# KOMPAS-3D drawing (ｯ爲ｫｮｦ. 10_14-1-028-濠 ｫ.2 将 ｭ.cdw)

Views: Вид 1
Referenced files in C:\Program Files\ASCON\KOMPAS-3D V10\Sys\: SPDS.lcs, Graphic.lcs
Referenced files: Планы вагончиков.cdw
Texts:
  Текст на чертеже
  Размерные надписи
  Шероховатость
  Линия-выноска #1
  Линия-выноска #2
  Линия-выноска #3
  Отклонения формы и база
  Заголовок таблицы
  Ячейка таблицы
  Стрелка вида
  Обозначение изменения
  Фигурная скобка
  Номер узла
  Марка координационной оси
  VRCB
  Выносная надпись
  Обозначение узла
  Марка/позиционное обозначение с линией-выноской
  Марка/позиционное обозначение на линии
  Марка/позиционное обозначение без линии-выноски
  Normal
  TXT
  Courier New Cyr
  txt
  Body Text
  heading 1
  Знак Знак Знак Знак Знак Знак
  Verdana
  Лит-Масса-Масштаб
  Материал-Предприятие
  MS Sans Serif
  Simplex
  Txt
  Title Specification
  Body Specification ( left align )
  Body Specificaton ( centered )
  Без имени
  Additional DXF text style 0
  Обычный
  Термин
  Список определений
  Адрес
  Цитаты
  Форматированный
  Courier New
  Z-конец формы
  Z-начало формы
  ТекстШаг1
  Денис
  heading 2
  AGOpus
  footer
  Title
  ООббыыччнныыйй
  Definition Term
  Definition List
  Address
  Blockquote
  Preformatted
  z-Bottom of Form
  z-Top of Form
  header
  heading 8
  heading 3
  heading 6
  heading 7
  russ
  ТТееррммиинн
  ССппииссоокк ооппррееддееллеенниийй
  ААддрреесс
  ЦЦииттааттыы
  ФФооррммааттиирроовваанннныыйй
  Z-ккооннеецц ффооррммыы
  Z-ннааччааллоо ффооррммыы
  Абзац Знак
  heading 4
  heading 5
  heading 9
  GOST 2.304 type A
  rustxt
  цепи
  ссылки
  Маркировка
  Подпись в квадратике
  табл
  ЗОНА_привяз
  маркировка
  ГОСТ_МНЕ
  ESK - Обозначение
  текст переноса
  Тексты. 3,2
  Body Text 3
  клеммы, контакты
  тексты табл
  ISOCP
  HeliosLight
  Pa3
  Pa1
  Шрифт 2.5
  Заголовки
  RUSTXT
  NormalParagraphStyle
  Три с половиной
  style2
  Table Contents
  Table Heading
  CNBNDG+TimesNewRoman
  Subtitle
  ISOCPEUR
  Текст 3,5
  Tahoma
  План ПС
  Существующее оборудование
  Дороги
  Оси, размеры
  Позиции,таблицы
  Топосъемка
  Демонтаж
  изм.1
  Вертикалка
  створ поз.2
  в.ЗРУ 108,86
  в.вх.105,84
  ЗРУ-110 кВ
  в.вх.105,54
  ЗРУ-35 кВ
  в.вх.105,48
  в.вх.103,67
  в.вх.105,89
  в.вх.103,72
  в.ЗРУ 108,68
  в.вх.105,56
  в.вх.105,47
  ЗРУ-6 кВ
  в.ош.103,82
  в.ош.103,84
  в.ош.103,80
  в.кр.п.111,27
  в.каб.112,57
  кр-100,99
  кр-100,45
  кр-100,41
  кр-101,03
  кр-101,02
  кр-100,56
  кр-100,70
  кр-100,94
  РП 1
  РП 2
  ТСН-2
  ТСН-1
  ПС 110 кВ Опорная
  Данная проектная документация разработана на основании технического задания на
  проектирование, межевого плана, кадастровой выписки о земельном участке №8900/212/12-15995
  от 14.09.2012г., материалов инженерно-топографических изысканий, выполненных ООО "Северный
  Стандарт" в 2012г.
  Технические решения,принятые в чертежах, соответствуют действующим нормам, правилам и
  стандартам.
  Номер
  на плане
  Экспликация зданий и сооружений
  Существующие здания и сооружения
  Проектируемые здания и сооружения
  Трансформатор силовой масляный трехфазный
  трехобмоточный ТДТН 40000/110 ХЛ1
  Реакторная 1Т
  Реакторная 2Т
  Маслосборник
  Очистная установка
  Резервуар
  Условные обозначения:
  - Аварийный маслоотвод
  - Напорный трубопровод подачи стоков
  - Трубопровод очищенного стока
  МП1
  МП2
  уг.2
  уг.1
  STROT_RGB_128_32_0_SC_1_THICK_0.18
  CONTI_RGB_0_0_0_THICK_0.18
  POLYLINE_STYLE_0.30_RGB_0_0_0
  POLYLINE_STYLE_0.18_RGB_0_0_0
  ACAD_ISO02W100_RGB_0_0_255_SC_1_THICK_0.3
  POLYLINE_STYLE_0.60_RGB_0_0_255
  ACAD_ISO02W100_RGB_0_0_0_SC_1_THICK_0.15
  POLYLINE_STYLE_0.18_RGB_255_0_0
  K5LT_AXLED_RGB_255_128_0_SC_1_THICK_0.09
  POLYLINE_STYLE_0.30_RGB_255_0_255
  POLYLINE_STYLE_0.20_RGB_0_0_0
  POLYLINE_STYLE_0.25_RGB_128_64_0
  POLYLINE_STYLE_0.18_RGB_128_64_0
  POLYLINE_STYLE_0.18_RGB_0_80_80
  K5LT_AXLED_RGB_255_128_0_SC_1_THICK_0.18
  K5LT_THIN_RGB_0_0_0_THICK_0.09
  K5LT_THIN_RGB_0_0_0_THICK_0.13
  СONTINUOUS_RGB_255_0_0_THICK_0.6
  ACAD_ISO04W100_RGB_255_0_0_SC_1_THICK_0.13
  Ультрас О 0,3
  K5LT_BASIC_RGB_0_0_255_THICK_0.2
  K5LT_BASIC_RGB_0_0_255_THICK_0.3
  K5LT_DASHED_RGB_255_255_0_SC_1_THICK_0.09
  POLYLINE_STYLE_0.30_RGB_0_0_255
  K5LT_THIN_INCLUDED_TO_HATCHING_RGB_168_0_168_THICK_0.09
  K5LT_REINFORCED_RGB_0_0_0_THICK_0.6
  Стили документа
  Железобетон
  Железобетон 1
  Н. контр
  Ромин
  Разраб.
  Реконструкция ПС 110 кВ Опорная
  (замена трансформаторов 16МВА на 40МВА)
  Галактионов
  Орлова
  Королева
  Кошель
  Аварийные маслостоки
Dimensions and other numbers on the sheet: 10/14-1-028-НК; 7; 3,2_; 2,5; 3.5; 2.5; 1,8; 2,5 (контакты, клеммы); 2.5 курсив; 2,5_3; 3,2 (надписи); 3,5_01; 2,5_01; 3,5_tabl; 5_заголовок; 2,3_; 3,2_зона не привяз; 2,5 грязносинь; 5,0_белый_подчёркнутый; 3,2; 3.2 фиол; 3,5; 5; 3,2 элементы; 3,2 линия; 3,2 таблица; 3.2 маркировка; 2.5_Э5_надписи; 2.5_Э5_ссылки; 2.5_кабель; 3.2; 2.5 надписи; 3,2 (Зоны); 3 и 5; 3.2 (текст); 1; 6; 2; 100,00; 3; 4.1; 4.2; 1,24; 3,68; 12; 1,73; 8,04; 1,72; 10,3; 0,62; 3,48; 10,32; 0,34; 3,34; 1,96; 2,45; 7,95; 5,25; 30; 20; 40; 8; 9; 10; 100,07; 100,13; 100,09; 100,11; 99,89; 99,97; 100,14; 100,26; 100,06; 100,05; 99,99; 99,86; 100,02; 100,25; 100,08; 100,22; 100,20; 100,03; 99,95; 100,63; 100,68; 100,34; 101,71; 101,13; 99,98; 99,91; 100,99; 101,12; 100,21; 100,29; 100,15; 100,12; 99,88; 100,18; 100,30; 100,41; 100,17; 100,48; 100,52; 100,27; 100,38; 100,24; 100,57; 100,16; 99,93; 101,41; 100,23; 7 пр.; 4 пр.; 110 кВ; 35 кВ; 3 пр.; 1950; 1000; 4.1-4.2; 1,5; 0,3; 0,4; 0,6; 11.12; 10/14-1-ИОС7.1-; 10.12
